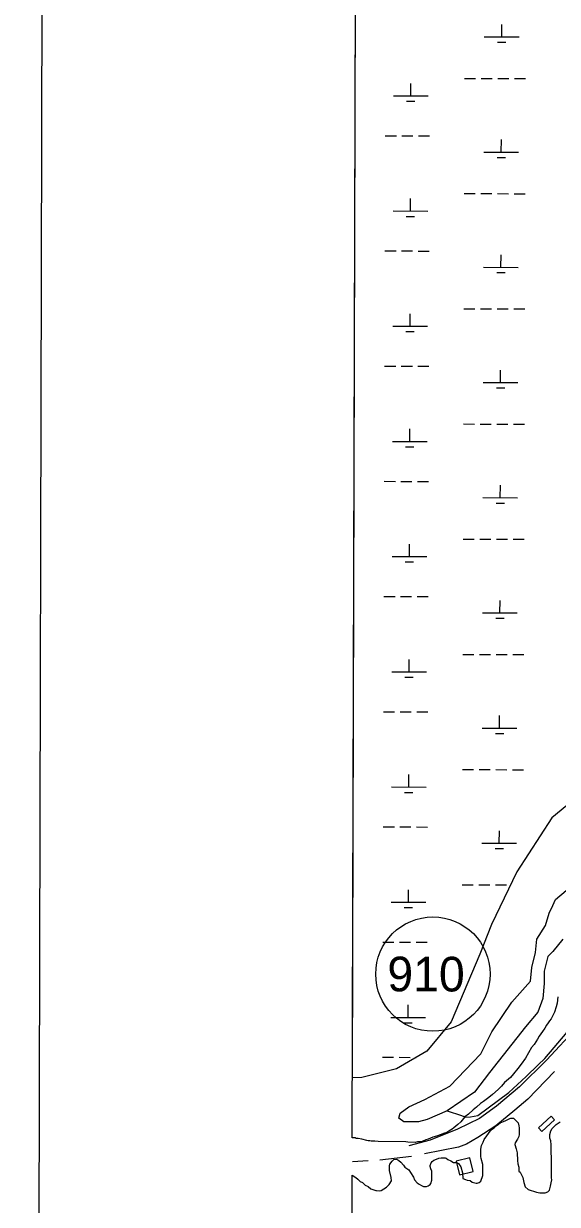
# Model space of a CAD drawing. Extents: x 3172297 to 3210190, y 958463 to 983887.
# Drawn here: x 3175632 to 3177171, y 977468 to 980876 of the extents above; entities that cross this region are included whole.
import ezdxf

# ---------------------------------------------------------------- set-up
doc = ezdxf.new("R2010")
doc.units = 0
for name, color, linetype in [('V-ANNO-SYMB', 7, 'Continuous'), ('V-BLDG-OTLN', 7, 'Continuous'), ('V-ROAD-CNTR', 7, 'Continuous'), ('V-ROAD-IDEN', 7, 'Continuous'), ('V-SITE-VEGE', 7, 'Continuous'), ('V-TOPO-SHOR', 7, 'Continuous'), ('V-WETL-SWMP', 7, 'Continuous')]:
    doc.layers.add(name, color=color, linetype=linetype)

msp = doc.modelspace()

# ---------------------------------------------------------------- linework, layer by layer
at = {"layer": 'V-ANNO-SYMB'}
msp.add_lwpolyline([(3175631.7, 959755.1), (3208714.8, 959673.3), (3208771.5, 982589.8), (3175688.4, 982671.6), (3175631.7, 959755.1)], dxfattribs=at)
at = {"layer": 'V-BLDG-OTLN'}
for points in [[(3177116.8, 977688.8), (3177153.4, 977722.7), (3177163, 977712.5), (3177126.3, 977678.5)], [(3176918.2, 977602.1), (3176879.3, 977592.6), (3176888.9, 977553.7), (3176927.7, 977563.3)]]:
    msp.add_lwpolyline(points, close=True, dxfattribs=at)
at = {"layer": 'V-ROAD-CNTR'}
msp.add_lwpolyline([(3177228.9, 977980.6), (3177139.7, 977884.7), (3177061.8, 977807), (3176995.1, 977751.7), (3176946.6, 977715.8), (3176882.5, 977684.9), (3176804.4, 977653.1), (3176742.4, 977637.4)], dxfattribs=at)
at = {"layer": 'V-ROAD-IDEN'}
msp.add_circle((3176812.1, 978132.9), 165, dxfattribs=at)
msp.add_circle((3176812.1, 978132.9), 165, dxfattribs=at)
at = {"layer": 'V-SITE-VEGE'}
for p, q in [((3176579.6, 977660.7), (3176592.5, 982109.6)), ((3177171.9, 978066.9), (3177170.2, 978049)), ((3177167, 978038), (3177163, 978022.5)), ((3177170.2, 978049), (3177167, 978038)), ((3177144.1, 977992.1), (3177139.4, 977985.9)), ((3177148, 977998.4), (3177144.1, 977992.1)), ((3177152.8, 978003.8), (3177148, 977998.4)), ((3177163, 978022.5), (3177152.8, 978003.8)), ((3177128.3, 977967.3), (3177118.9, 977954)), ((3177134.6, 977976.6), (3177128.3, 977967.3)), ((3177139.4, 977985.9), (3177134.6, 977976.6)), ((3177103.9, 977929.9), (3177096.8, 977920.6)), ((3177113.3, 977944.7), (3177103.9, 977929.9)), ((3177118.9, 977954), (3177113.3, 977944.7)), ((3177078.6, 977890.3), (3177066.8, 977873.2)), ((3177096.8, 977920.6), (3177078.6, 977890.3)), ((3177056.6, 977860.8), (3177044.8, 977845.2)), ((3177066.8, 977873.2), (3177056.6, 977860.8)), ((3177035.3, 977834.4), (3177018.8, 977819.6)), ((3177044.8, 977845.2), (3177035.3, 977834.4)), ((3176999.9, 977799.5), (3176984.2, 977785.5)), ((3177010.2, 977809.6), (3176999.9, 977799.5)), ((3177018.8, 977819.6), (3177010.2, 977809.6)), ((3176949.7, 977759.2), (3176937.9, 977749.1)), ((3176957.6, 977765.4), (3176949.7, 977759.2)), ((3176973.2, 977776.2), (3176957.6, 977765.4)), ((3176984.2, 977785.5), (3176973.2, 977776.2)), ((3176904.2, 977720.5), (3176892.4, 977706.5)), ((3176914.4, 977728.2), (3176904.2, 977720.5)), ((3176927.7, 977741.4), (3176914.4, 977728.2)), ((3176937.9, 977749.1), (3176927.7, 977741.4)), ((3176868, 977685.6), (3176857.8, 977679.4)), ((3176872, 977688.7), (3176868, 977685.6)), ((3176883.7, 977698.7), (3176872, 977688.7)), ((3176892.4, 977706.5), (3176883.7, 977698.7)), ((3176980.4, 977683.3), (3176988.3, 977689.5)), ((3176988.3, 977689.5), (3176996.9, 977697.2)), ((3176996.9, 977697.2), (3177001.6, 977699.5)), ((3177001.6, 977699.5), (3177007.1, 977704.2)), ((3177007.1, 977704.2), (3177011, 977705.7)), ((3177011, 977705.7), (3177015.7, 977707.2)), ((3177015.7, 977707.2), (3177022, 977710.3)), ((3177022, 977710.3), (3177025.9, 977712.6)), ((3177025.9, 977712.6), (3177033.7, 977715.7)), ((3177033.7, 977715.7), (3177036.9, 977717.2)), ((3177036.9, 977717.2), (3177044.7, 977717.2)), ((3177044.7, 977717.2), (3177057.9, 977703.8)), ((3177057.9, 977703.8), (3177060.1, 977694.5)), ((3177060.1, 977694.5), (3177060.9, 977689)), ((3177060.9, 977689), (3177060.8, 977669.5)), ((3177152.2, 977680.6), (3177156.1, 977687.6)), ((3177156.1, 977687.6), (3177167.9, 977699.2)), ((3177167.9, 977699.2), (3177178.9, 977706.9)), ((3176582.9, 977660.1), (3176579.6, 977660.7)), ((3176587.6, 977660.1), (3176582.9, 977660.1)), ((3176590.7, 977658.5), (3176587.6, 977660.1)), ((3176596.9, 977658.5), (3176590.7, 977658.5)), ((3176607.1, 977656.1), (3176596.9, 977658.5)), ((3176621.1, 977652.9), (3176607.1, 977656.1)), ((3176625, 977652), (3176621.1, 977652.9)), ((3176630.5, 977652), (3176625, 977652)), ((3176634.4, 977650.4), (3176630.5, 977652)), ((3176644.5, 977650.4), (3176634.4, 977650.4)), ((3176654.6, 977649.5), (3176644.5, 977650.4)), ((3176791.3, 977654.1), (3176781.1, 977649.5)), ((3176798.4, 977656.4), (3176791.3, 977654.1)), ((3176811.7, 977661.7), (3176798.4, 977656.4)), ((3176822.6, 977664.8), (3176811.7, 977661.7)), ((3176835.9, 977669.4), (3176822.6, 977664.8)), ((3176842.2, 977672.5), (3176835.9, 977669.4)), ((3176852.4, 977675.5), (3176842.2, 977672.5)), ((3176857.8, 977679.4), (3176852.4, 977675.5)), ((3176956.8, 977647.5), (3176960, 977655.3)), ((3176960, 977655.3), (3176967.8, 977666.2)), ((3176967.8, 977666.2), (3176972.6, 977673.2)), ((3176972.6, 977673.2), (3176980.4, 977683.3)), ((3177056, 977656.2), (3177049.7, 977646.1)), ((3177060, 977664), (3177056, 977656.2)), ((3177060.8, 977669.5), (3177060, 977664)), ((3177148.9, 977659.5), (3177149, 977665)), ((3177152, 977651.7), (3177148.9, 977659.5)), ((3177149, 977669.7), (3177152.2, 977680.6)), ((3177149, 977665), (3177149, 977669.7)), ((3177153.5, 977640), (3177152, 977651.7)), ((3176734.3, 977649), (3176654.6, 977649.5)), ((3176739.7, 977647.4), (3176734.3, 977649)), ((3176760.8, 977647.2), (3176739.7, 977647.4)), ((3176767.1, 977648.8), (3176760.8, 977647.2)), ((3176777.2, 977648.7), (3176767.1, 977648.8)), ((3176781.1, 977649.5), (3176777.2, 977648.7)), ((3176950.3, 977606.2), (3176950.4, 977628)), ((3176950.4, 977628), (3176952, 977638.2)), ((3176952, 977638.2), (3176956.8, 977647.5)), ((3177049.7, 977646.1), (3177048.1, 977640.7)), ((3177048.1, 977640.7), (3177051.9, 977628.1)), ((3177051.9, 977628.1), (3177055, 977617.2)), ((3177055, 977617.2), (3177055.6, 977595.3)), ((3177153.3, 977615.8), (3177153.5, 977640)), ((3177154, 977605.6), (3177153.3, 977615.8)), ((3176687, 977579.8), (3176687.8, 977584.5)), ((3176687.8, 977584.5), (3176694.9, 977593)), ((3176694.9, 977593), (3176699.6, 977597.7)), ((3176699.6, 977597.7), (3176708.2, 977598.4)), ((3176708.2, 977598.4), (3176713.6, 977595.2)), ((3176713.6, 977595.2), (3176719.1, 977590.5)), ((3176719.1, 977590.5), (3176726.8, 977581.1)), ((3176804.1, 977580.6), (3176807.3, 977588.4)), ((3176807.3, 977588.4), (3176809.6, 977591.5)), ((3176809.6, 977591.5), (3176815.1, 977596.1)), ((3176815.1, 977596.1), (3176817.5, 977596.9)), ((3176817.5, 977596.9), (3176829.2, 977601.5)), ((3176829.2, 977601.5), (3176836.3, 977602.2)), ((3176836.3, 977602.2), (3176844.1, 977602.2)), ((3176844.1, 977602.2), (3176847.2, 977603)), ((3176847.2, 977603), (3176850.3, 977601.4)), ((3176850.3, 977601.4), (3176855, 977597.4)), ((3176855, 977597.4), (3176863.5, 977593.5)), ((3176863.5, 977593.5), (3176871.3, 977589.5)), ((3176871.3, 977589.5), (3176874.4, 977588.7)), ((3176874.4, 977588.7), (3176879.9, 977588.7)), ((3176879.9, 977588.7), (3176886.1, 977586.3)), ((3176886.1, 977586.3), (3176892.3, 977576.9)), ((3176951, 977600.7), (3176950.3, 977606.2)), ((3176955.6, 977583.5), (3176951, 977600.7)), ((3176956.3, 977577.2), (3176955.6, 977583.5)), ((3177055.6, 977595.3), (3177057.1, 977585.2)), ((3177057.1, 977585.2), (3177059.4, 977575.8)), ((3177153.6, 977544.7), (3177154, 977605.6)), ((3176578.8, 977402.4), (3176579.2, 977552.2)), ((3176579.2, 977552.2), (3176589.9, 977546.1)), ((3176686.9, 977565.8), (3176687, 977579.8)), ((3176691.4, 977545.4), (3176686.9, 977565.8)), ((3176726.8, 977581.1), (3176731.5, 977575.6)), ((3176731.5, 977575.6), (3176742.3, 977567.7)), ((3176742.3, 977567.7), (3176747.7, 977559.9)), ((3176747.7, 977559.9), (3176756.2, 977546.6)), ((3176804.1, 977577.5), (3176804.1, 977580.6)), ((3176806.4, 977570.4), (3176804.1, 977577.5)), ((3176808.7, 977564.2), (3176806.4, 977570.4)), ((3176809.3, 977547), (3176808.7, 977564.2)), ((3176892.3, 977576.9), (3176896.9, 977559.7)), ((3176896.9, 977559.7), (3176898.3, 977543.3)), ((3176949.8, 977535.1), (3176956.2, 977551.5)), ((3176956.2, 977551.5), (3176956.3, 977577.2)), ((3177059.4, 977575.8), (3177060.1, 977569.5)), ((3177060.1, 977569.5), (3177060.1, 977564.1)), ((3177060.1, 977564.1), (3177063.2, 977560.9)), ((3177063.2, 977560.9), (3177070.9, 977545.3)), ((3176589.9, 977546.1), (3176595.4, 977540.6)), ((3176595.4, 977540.6), (3176602.4, 977534.3)), ((3176602.4, 977534.3), (3176608.6, 977531.1)), ((3176608.6, 977531.1), (3176617.1, 977524.1)), ((3176617.1, 977524.1), (3176624.9, 977520.1)), ((3176624.9, 977520.1), (3176632.7, 977513)), ((3176663.1, 977508.1), (3176678, 977518.2)), ((3176678, 977518.2), (3176685.8, 977525.2)), ((3176685.8, 977525.2), (3176692.2, 977536.1)), ((3176692.2, 977536.1), (3176691.4, 977545.4)), ((3176756.2, 977546.6), (3176758.5, 977538.7)), ((3176758.5, 977538.7), (3176766.3, 977530.1)), ((3176766.3, 977530.1), (3176772.5, 977526.2)), ((3176772.5, 977526.2), (3176779.5, 977522.2)), ((3176779.5, 977522.2), (3176785, 977519.8)), ((3176785, 977519.8), (3176793.5, 977519.8)), ((3176793.5, 977519.8), (3176798.2, 977522.1)), ((3176798.2, 977522.1), (3176804.5, 977525.9)), ((3176804.5, 977525.9), (3176806.1, 977528.3)), ((3176806.1, 977528.3), (3176808.5, 977537.6)), ((3176808.5, 977537.6), (3176809.3, 977547)), ((3176898.3, 977543.3), (3176906.1, 977540.1)), ((3176906.1, 977540.1), (3176910.8, 977538.5)), ((3176910.8, 977538.5), (3176919.4, 977536.9)), ((3176919.4, 977536.9), (3176924.8, 977532.2)), ((3176924.8, 977532.2), (3176936.5, 977529.8)), ((3176936.5, 977529.8), (3176939.6, 977529)), ((3176939.6, 977529), (3176945.1, 977531.3)), ((3176945.1, 977531.3), (3176949.8, 977535.1)), ((3177070.9, 977545.3), (3177073.9, 977531.2)), ((3177073.9, 977531.2), (3177078.5, 977518.7)), ((3177078.5, 977518.7), (3177087, 977510.8)), ((3177147.9, 977509.6), (3177151.1, 977520.5)), ((3177151.1, 977520.5), (3177152.8, 977529.9)), ((3177152.8, 977529.9), (3177155.2, 977539.2)), ((3177155.2, 977539.2), (3177153.6, 977544.7)), ((3176632.7, 977513), (3176635.8, 977512.2)), ((3176635.8, 977512.2), (3176647.5, 977508.2)), ((3176647.5, 977508.2), (3176649.8, 977508.2)), ((3176649.8, 977508.2), (3176657.6, 977507.4)), ((3176657.6, 977507.4), (3176663.1, 977508.1)), ((3177087, 977510.8), (3177111.2, 977503.6)), ((3177111.2, 977503.6), (3177120.6, 977501.2)), ((3177120.6, 977501.2), (3177136.2, 977501.1)), ((3177136.2, 977501.1), (3177143.2, 977504.2)), ((3177143.2, 977504.2), (3177147.9, 977509.6))]:
    msp.add_line(p, q, dxfattribs=at)
at = {"layer": 'V-TOPO-SHOR'}
for p, q in [((3176625.1, 977594.3), (3176580.4, 977590.9)), ((3176750.1, 977606.5), (3176659, 977596))]:
    msp.add_line(p, q, dxfattribs=at)
for points in [[(3177186.4, 978234), (3177157.7, 978198.3), (3177143.4, 978184.1), (3177132.6, 978141.2), (3177132.5, 978105.5), (3177128.8, 978062.7), (3177114.5, 978023.4), (3177078.6, 977980.7), (3176974.8, 977848.8), (3176931.8, 977791.8), (3176853.1, 977738.4), (3176795.9, 977713.5), (3176770.8, 977706.5), (3176745.9, 977706.5), (3176728, 977706.6), (3176713.7, 977717.3), (3176717.3, 977731.6), (3176742.4, 977749.4), (3176788.9, 977770.7), (3176860.4, 977809.8), (3176949.9, 977902.4), (3176982.2, 977966.6), (3177039.5, 978052.2), (3177093.2, 978112.8), (3177096.9, 978152), (3177107.7, 978194.9), (3177111.4, 978234.1), (3177136.5, 978273.4), (3177147.3, 978309), (3177158.1, 978330.4), (3177165.3, 978348.3), (3177233.2, 978405.3)], [(3176853.1, 977738.4), (3176894.5, 977724.5), (3176906.1, 977720), (3176920.4, 977720.8), (3176941.9, 977724.3), (3177031.3, 977791.1), (3177080.5, 977837.4), (3177115.4, 977871.2), (3177135.1, 977889), (3177264, 978041.4), (3177343.7, 978134)], [(3177163.1, 977851.9), (3177086.2, 977771.8), (3177048.6, 977739.7), (3176993.1, 977695.2), (3176941.3, 977661.4), (3176909.1, 977641.8), (3176885.8, 977633), (3176787.6, 977613.6)]]:
    msp.add_lwpolyline(points, dxfattribs=at)
at = {"layer": 'V-WETL-SWMP'}
for p, q in [((3176580.1, 977833.3), (3176592.5, 982109.6)), ((3177010.3, 980837.8), (3177010.4, 980873.8)), ((3176960.3, 980837.9), (3177060.3, 980837.7)), ((3176998.2, 980822.4), (3177022.2, 980822.4)), ((3176903.1, 980718.1), (3176935.1, 980718)), ((3176951.1, 980718), (3176983.1, 980717.9)), ((3176999.1, 980717.8), (3177031.1, 980717.8)), ((3177047.1, 980717.7), (3177079.1, 980717.6)), ((3176748.4, 980667.7), (3176748.5, 980703.7)), ((3176698.4, 980667.9), (3176798.3, 980667.6)), ((3176736.3, 980652.4), (3176760.3, 980652.3)), ((3176674.6, 980552.6), (3176706.6, 980552.5)), ((3176722.6, 980552.4), (3176754.6, 980552.4)), ((3176770.6, 980552.3), (3176802.6, 980552.2)), ((3177009.3, 980505.3), (3177009.4, 980541.3)), ((3176959.3, 980505.5), (3177059.3, 980505.2)), ((3176997.2, 980489.9), (3177021.2, 980489.9)), ((3176902.1, 980385.6), (3176934.1, 980385.5)), ((3176950.1, 980385.5), (3176982.1, 980385.4)), ((3176998.1, 980385.4), (3177030.1, 980385.3)), ((3177046.1, 980385.2), (3177078.1, 980385.2)), ((3176747.4, 980335.3), (3176747.5, 980371.2)), ((3176697.4, 980335.4), (3176797.4, 980335.1)), ((3176735.3, 980319.9), (3176759.3, 980319.8)), ((3176673.6, 980220.1), (3176705.6, 980220)), ((3176721.6, 980220), (3176753.6, 980219.9)), ((3176769.6, 980219.8), (3176801.6, 980219.8)), ((3177008.3, 980172.8), (3177008.4, 980208.8)), ((3176958.3, 980173), (3177058.3, 980172.7)), ((3176996.3, 980157.5), (3177020.3, 980157.4)), ((3176746.4, 980002.8), (3176746.5, 980038.8)), ((3176901.1, 980053.1), (3176933.1, 980053)), ((3176949.1, 980053), (3176981.1, 980052.9)), ((3176997.1, 980052.9), (3177029.1, 980052.8)), ((3177045.1, 980052.7), (3177077.1, 980052.7)), ((3176696.4, 980002.9), (3176796.4, 980002.7)), ((3176734.4, 979987.4), (3176758.4, 979987.3)), ((3176672.7, 979887.6), (3176704.7, 979887.5)), ((3176720.7, 979887.5), (3176752.7, 979887.4)), ((3176768.7, 979887.4), (3176800.7, 979887.3)), ((3177007.3, 979840.4), (3177007.4, 979876.3)), ((3176957.3, 979840.5), (3177057.3, 979840.2)), ((3176995.3, 979825), (3177019.3, 979824.9)), ((3176745.4, 979670.3), (3176745.5, 979706.3)), ((3176900.2, 979720.6), (3176932.2, 979720.5)), ((3176948.2, 979720.5), (3176980.2, 979720.4)), ((3176996.2, 979720.4), (3177028.1, 979720.3)), ((3177044.1, 979720.3), (3177076.1, 979720.2)), ((3176695.4, 979670.4), (3176795.4, 979670.2)), ((3176733.4, 979654.9), (3176757.4, 979654.8)), ((3176671.7, 979555.1), (3176703.7, 979555)), ((3176719.7, 979555), (3176751.7, 979554.9)), ((3176767.7, 979554.9), (3176799.7, 979554.8)), ((3177006.4, 979507.9), (3177006.5, 979543.9)), ((3176956.4, 979508), (3177056.4, 979507.7)), ((3176994.3, 979492.5), (3177018.3, 979492.4)), ((3176899.2, 979388.1), (3176931.2, 979388.1)), ((3176947.2, 979388), (3176979.2, 979387.9)), ((3176744.5, 979337.8), (3176744.6, 979373.8)), ((3176995.2, 979387.9), (3177027.2, 979387.8)), ((3177043.2, 979387.8), (3177075.2, 979387.7)), ((3176694.5, 979337.9), (3176794.5, 979337.7)), ((3176732.4, 979322.4), (3176756.4, 979322.3)), ((3176670.7, 979222.6), (3176702.7, 979222.5)), ((3176718.7, 979222.5), (3176750.7, 979222.4)), ((3176766.7, 979222.4), (3176798.7, 979222.3)), ((3177005.4, 979175.4), (3177005.5, 979211.4)), ((3176955.4, 979175.5), (3177055.4, 979175.3)), ((3176993.4, 979160), (3177017.4, 979159.9)), ((3176898.2, 979055.6), (3176930.2, 979055.6)), ((3176946.2, 979055.5), (3176978.2, 979055.4)), ((3176994.2, 979055.4), (3177026.2, 979055.3)), ((3177042.2, 979055.3), (3177074.2, 979055.2)), ((3176743.5, 979005.3), (3176743.6, 979041.3)), ((3176693.5, 979005.4), (3176793.5, 979005.2)), ((3176731.4, 978989.9), (3176755.4, 978989.9)), ((3176669.7, 978890.1), (3176701.7, 978890.1)), ((3176717.7, 978890), (3176749.7, 978889.9)), ((3176765.7, 978889.9), (3176797.7, 978889.8)), ((3177004.4, 978842.9), (3177004.5, 978878.9)), ((3176954.4, 978843), (3177054.4, 978842.8)), ((3176992.4, 978827.5), (3177016.4, 978827.4)), ((3176742.5, 978672.8), (3176742.6, 978708.8)), ((3176897.2, 978723.2), (3176929.2, 978723.1)), ((3176945.2, 978723), (3176977.2, 978723)), ((3176993.2, 978722.9), (3177025.2, 978722.8)), ((3177041.2, 978722.8), (3177073.2, 978722.7)), ((3176692.5, 978673), (3176792.5, 978672.7)), ((3176730.5, 978657.4), (3176754.5, 978657.4)), ((3177251.7, 978663.9), (3177155.1, 978584.2)), ((3177155.1, 978584.2), (3177054.1, 978428.1)), ((3176668.8, 978557.6), (3176700.8, 978557.6)), ((3176716.8, 978557.5), (3176748.8, 978557.4)), ((3176764.8, 978557.4), (3176796.8, 978557.3)), ((3177003.5, 978510.4), (3177003.6, 978546.4)), ((3176953.5, 978510.5), (3177053.4, 978510.3)), ((3176991.4, 978495), (3177015.4, 978495)), ((3177054.1, 978428.1), (3176981.2, 978276.4)), ((3176741.5, 978340.3), (3176741.6, 978376.3)), ((3176896.3, 978390.7), (3176928.3, 978390.6)), ((3176944.3, 978390.6), (3176976.3, 978390.5)), ((3176992.3, 978390.4), (3177024.3, 978390.4)), ((3176691.5, 978340.5), (3176791.5, 978340.2)), ((3176729.5, 978324.9), (3176753.5, 978324.9)), ((3176981.2, 978276.4), (3176947, 978190.1)), ((3176667.8, 978225.2), (3176699.8, 978225.1)), ((3176715.8, 978225), (3176747.8, 978225)), ((3176763.8, 978224.9), (3176795.8, 978224.8)), ((3176947, 978190.1), (3176864.5, 977994.8)), ((3176740.6, 978007.9), (3176740.7, 978043.8)), ((3176690.6, 978008), (3176790.6, 978007.7)), ((3176728.5, 977992.5), (3176752.5, 977992.4)), ((3176864.5, 977994.8), (3176794.4, 977910.3)), ((3176666.8, 977892.7), (3176698.8, 977892.6)), ((3176794.4, 977910.3), (3176707.4, 977859.3)), ((3176714.8, 977892.6), (3176746.8, 977892.5)), ((3176762.8, 977892.4), (3176763.9, 977892.4)), ((3176707.4, 977859.3), (3176607.3, 977834.2)), ((3176607.3, 977834.2), (3176580.1, 977833.3))]:
    msp.add_line(p, q, dxfattribs=at)

# ---------------------------------------------------------------- texts
at = {"layer": 'V-ROAD-IDEN'}
msp.add_text('910', height=100, rotation=359.8583, dxfattribs=at).set_placement((3176680.5, 978083.2))

doc.saveas('drawing.dxf')
